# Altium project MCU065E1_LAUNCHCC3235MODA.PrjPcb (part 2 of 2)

## Sheet MCU065E1_XDS110_Circuit.SchDoc: XDS110_Circuit
size 431 x 279 mm; Date: Not shown in title block; ApprovedBy: Not shown in title block; CheckedBy: Not shown in title block; Author: Not shown in title block; CompanyName: Not shown in title block; DrawnBy: Seong Kim; Engineer: Not shown in title block; Organization: Not shown in title block; Address1: Not shown in title block; Address2: Not shown in title block; Address3: Not shown in title block; Address4: Not shown in title block; DocumentNumber: 2; Revision: Use project parameter SCH_Rev; SheetNumber: 2; SheetTotal: 6; PageSetup: Record=PageOptions¦CenterHorizontal=True¦CenterVertical=True¦PrintScale=1.00¦XCorrection=1.00¦YCorrection=1.00¦PrintKind=0¦BorderSize=5000000¦LeftOffset=0¦BottomOffset=0¦Orientation=2¦PaperLength=1000¦PaperWidth=1000¦Scale=100¦PaperSource=15¦PrintQuality=600¦MediaType=1¦DitherType=10¦PaperKind=Letter¦PrintScaleMode=1
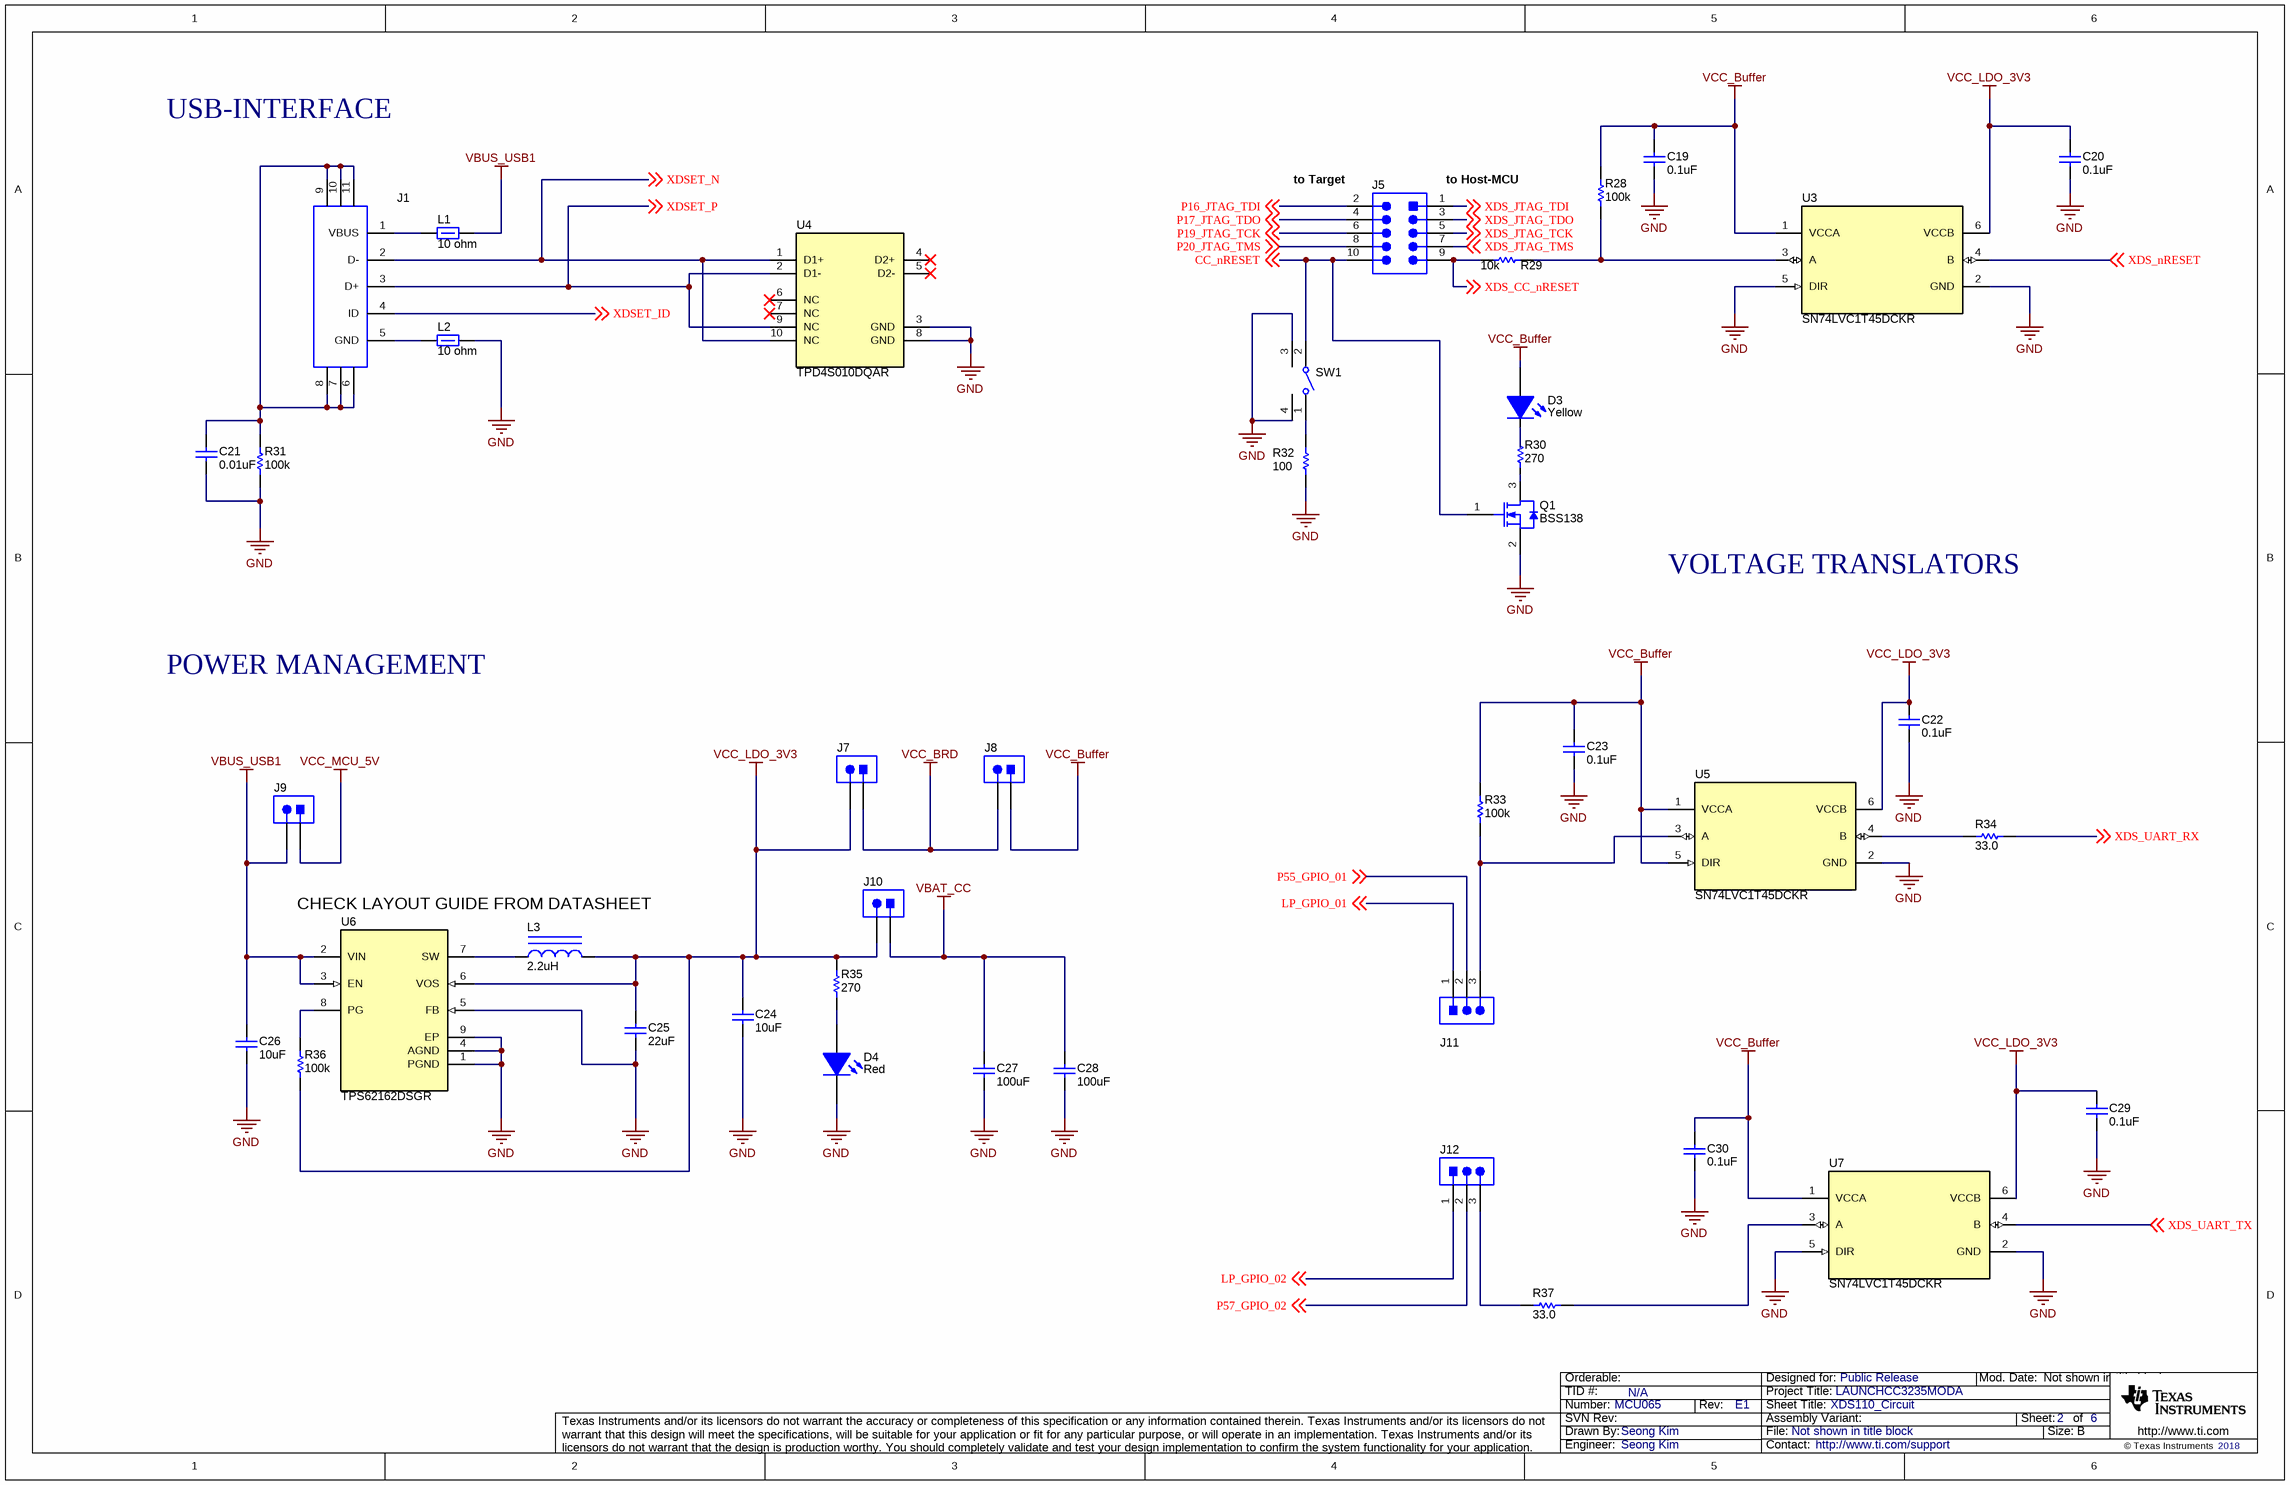
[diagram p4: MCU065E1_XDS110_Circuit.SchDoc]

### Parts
C19  ValueDisplayed: 0.1uF  [0402]  (hidden comment: GRM155R61A104KA01D)
C20  ValueDisplayed: 0.1uF  [0402]  (hidden comment: GRM155R61A104KA01D)
C21  ValueDisplayed: 0.01uF  [0402]  (hidden comment: GRM155R71C103KA01D)
C22  ValueDisplayed: 0.1uF  [0402]  (hidden comment: GRM155R61A104KA01D)
C23  ValueDisplayed: 0.1uF  [0402]  (hidden comment: GRM155R61A104KA01D)
C24  ValueDisplayed: 10uF  [0805]  (hidden comment: CMP-0008285-2)
C25  ValueDisplayed: 22uF  [0805_HV]  (hidden comment: CMP-0007826-2)
C26  ValueDisplayed: 10uF  [0805]  (hidden comment: CMP-0008285-2)
C27  ValueDisplayed: 100uF  [1206_180M]  (hidden comment: CMP-0008934-2)
C28  ValueDisplayed: 100uF  [1206_180]  (hidden comment: CMP-0008934-2)
C29  ValueDisplayed: 0.1uF  [0402]  (hidden comment: GRM155R61A104KA01D)
C30  ValueDisplayed: 0.1uF  [0402]  (hidden comment: GRM155R61A104KA01D)
D3  value Yellow  [WL-SMCW_YELLOW]  (hidden comment: CMP-0002892-2)
D4  value Red  [SML-31_Red]  (hidden comment: CMP-0002871-1)
J1  1051640001  [Molex_1051640001]  (value not drawn)
J5  61301021121  [WURTH_61301021121]  (value not drawn)
J7  CMP-0054794-1  [WURTH_61300211121]  (value not drawn)
J8  CMP-0054794-1  [WURTH_61300211121]  (value not drawn)
J9  CMP-0054794-1  [WURTH_61300211121]  (value not drawn)
J10  CMP-0054794-1  [WURTH_61300211121]  (value not drawn)
J11  61300311121  [WURTH_61300311121]  (value not drawn)
J12  61300311121  [WURTH_61300311121]  (value not drawn)
L1  ValueDisplayed: 10 ohm  [0402]  (hidden comment: BLM15AG100SN1D)
L2  ValueDisplayed: 10 ohm  [0402]  (hidden comment: BLM15AG100SN1D)
L3  ValueDisplayed: 2.2uH  [0805]  (hidden comment: CMP-0059580-1)
Q1  BSS138  [SOT-23]
R28  ValueDisplayed: 100k  [0402]  (hidden comment: CRCW0402100KJNED)
R29  ValueDisplayed: 10k  [0402]  (hidden comment: CRCW040210K0JNED)
R30  ValueDisplayed: 270  [0603]  (hidden comment: CMP-0025765-4)
R31  ValueDisplayed: 100k  [0603]  (hidden comment: CRCW0603100KJNEAC)
R32  ValueDisplayed: 100  [0402]  (hidden comment: CMP-0026656-1)
R33  ValueDisplayed: 100k  [0402]  (hidden comment: CRCW0402100KJNED)
R34  ValueDisplayed: 33.0  [0402]  (hidden comment: ERJ-2RKF33R0X)
R35  ValueDisplayed: 270  [0603]  (hidden comment: CMP-0025765-4)
R36  ValueDisplayed: 100k  [0402]  (hidden comment: CMP-0026823-3)
R37  ValueDisplayed: 33.0  [0402]  (hidden comment: ERJ-2RKF33R0X)
SW1  TL3330AF260QG  [SW_TL3330]  (value not drawn)
U3  SN74LVC1T45DCKR  [DCK0006A_N]
U4  TPD4S010DQAR  [DQA0010A]
U5  SN74LVC1T45DCKR  [DCK0006A_N]
U6  PartNumber: TPS62162DSGR  [DSG0008A]  (hidden comment: CMP-0037789-2)
U7  SN74LVC1T45DCKR  [DCK0006A_N]

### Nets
GND: C19.2 C20.2 C21.2 C22.2 C23.2 C24.2 C25.2 C26.2 C27.2 C28.2 C29.2 C30.2 D4.1(K) L2.2 Q1.2(S) R31.1 R32.1 SW1.3 SW1.4 U3.2(GND) U3.5(DIR) U4.3(GND) U4.8(GND) U5.2(GND) U6.1(PGND) U6.4(AGND) U6.5(FB) U6.9(EP) U7.2(GND) U7.5(DIR)
VBAT_CC: C27.1 C28.1 J10.1
VBUS_USB1: C26.1 J9.2 L1.2 U6.2(VIN) U6.3(EN)
VCC_BRD: J7.1 J8.2
VCC_Buffer: C19.1 C23.1 C30.1 D3.2(A) J8.1 R28.2 R33.2 U3.1(VCCA) U5.1(VCCA) U5.5(DIR) U7.1(VCCA)
VCC_LDO_3V3: C20.1 C22.1 C24.1 C25.1 C29.1 J7.2 J10.2 L3.2 R35.1 R36.2 U3.6(VCCB) U5.6(VCCB) U6.6(VOS) U7.6(VCCB)
VCC_MCU_5V: J9.1
CC_nRESET: J5.10 Q1.1(G) SW1.2 ; off-sheet CC_nRESET
LP_GPIO_01: J11.1 ; off-sheet LP_GPIO_01
LP_GPIO_02: J12.1 ; off-sheet LP_GPIO_02
P16_JTAG_TDI: J5.2 ; off-sheet P16_JTAG_TDI
P17_JTAG_TDO: J5.4 ; off-sheet P17_JTAG_TDO
P19_JTAG_TCK: J5.6 ; off-sheet P19_JTAG_TCK
P20_JTAG_TMS: J5.8 ; off-sheet P20_JTAG_TMS
P55_GPIO_01: J11.2 ; off-sheet P55_GPIO_01
P57_GPIO_02: J12.2 ; off-sheet P57_GPIO_02
XDS_CC_nRESET: J5.9 R29.1 ; off-sheet XDS_CC_nRESET
XDS_JTAG_TCK: J5.5 ; off-sheet XDS_JTAG_TCK
XDS_JTAG_TDI: J5.1 ; off-sheet XDS_JTAG_TDI
XDS_JTAG_TDO: J5.3 ; off-sheet XDS_JTAG_TDO
XDS_JTAG_TMS: J5.7 ; off-sheet XDS_JTAG_TMS
XDS_nRESET: U3.4(B) ; off-sheet XDS_nRESET
XDS_UART_RX: R34.2 ; off-sheet XDS_UART_RX
XDS_UART_TX: U7.4(B) ; off-sheet XDS_UART_TX
XDSET_ID: J1.4(ID) ; off-sheet XDSET_ID
XDSET_N: J1.2(D-) U4.1(D1+) U4.10(NC) ; off-sheet XDSET_N
XDSET_P: J1.3(D+) U4.2(D1-) U4.9(NC) ; off-sheet XDSET_P
NetC21_1: C21.1 J1.6 J1.7 J1.8 J1.9 J1.10 J1.11 R31.2
NetD3_1: D3.1(K) R30.2
NetD4_2: D4.2(A) R35.2
NetJ1_1: J1.1(VBUS) L1.1
NetJ1_5: J1.5(GND) L2.1
NetJ11_3: J11.3 R33.1 U5.3(A)
NetJ12_3: J12.3 R37.1
NetL3_1: L3.1 U6.7(SW)
NetQ1_3: Q1.3(D) R30.1
NetR28_1: R28.1 R29.2 U3.3(A)
NetR32_2: R32.2 SW1.1
NetR34_1: R34.1 U5.4(B)
NetR36_1: R36.1 U6.8(PG)
NetR37_2: R37.2 U7.3(A)

Not connected (* = marked no-connect by the designer): U4 4(D2+)* 5(D2-)* 6(NC)* 7(NC)*

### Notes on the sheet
- USB-INTERFACE
- (near J5) to Target
- (near J5) to Host-MCU
- VOLTAGE TRANSLATORS
- POWER MANAGEMENT
- CHECK LAYOUT GUIDE FROM DATASHEET

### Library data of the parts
C19 C20 C22 C23 C29 C30 = CMP-0006562-2: CAP, CERM, 0.1 uF, 10 V, +/- 10%, X5R, 0402; Manufacturer: MuRata; TaMin_C: -55°C; Polarized: N; SizeAreaWB_mm2: 3; Value1: Unknown; U/M: EA; Value: 0.1uF; TaMax_C: 85°C; SizeZ_mm: 0.6; SizeX_mm: 1; SizeY_mm: 0.5; Value2: 10V; CompType: Capacitor; Cap_F: 100nF; AEC Category: Q200
C21 = CMP-0006639-2: CAP, CERM, 0.01 uF, 16 V, +/- 10%, X7R, 0402; Manufacturer: MuRata; TaMin_C: -55°C; Polarized: N; SizeAreaWB_mm2: 3; Value1: Unknown; U/M: EA; Value: 0.01uF; TaMax_C: 125°C; SizeZ_mm: 0.6; SizeX_mm: 1; SizeY_mm: 0.5; Value2: 16V; CompType: Capacitor; Cap_F: 10nF; AEC Category: Q200
C24 C26 = CMP-0008285-2: CAP, CERM, 10 uF, 10 V, +/- 10%, X5R, 0805; PartNumber: GRM21BR61A106KE19L; Manufacturer: MuRata; Alternate PartNumber: CL21A106KPFNNNE; Alternate Manufacturer: SAMSUNG; Polarized: N; CompType: Capacitor; Value: 10uF; U/M: EA; Cap_F: 10µF; ESR_ohm: 2m; Value1: 0.002 ohm; VDC_V: 10V; TaMin_C: -55°C; TaMax_C: 85°C; SizeAreaWB_mm2: 6.75; SizeZ_mm: 1.45; SizeX_mm: 2; SizeY_mm: 1.25; SizeArea_mm2: 2.5; AEC Category: Q200
C25 = CMP-0007826-2: CAP, CERM, 22 uF, 16 V, +/- 10%, X5R, 0805; PartNumber: C2012X5R1C226K125AC; Manufacturer: TDK; Alternate PartNumber: ----; Polarized: N; CompType: Capacitor; Value: 22uF; U/M: EA; Cap_F: 22µF; Value1: Unknown; VDC_V: 16V; TaMin_C: -55°C; TaMax_C: 85°C; Cap_Case: 0805; AEC Category: Q200; SizeAreaWB_mm2: 6.75; SizeZ_mm: 1.45; SizeX_mm: 2; SizeY_mm: 1.25; SizeArea_mm2: 2.5
C27 C28 = CMP-0008934-2: CAP, CERM, 100 uF, 6.3 V, +/- 20%, X5R, 1206; PartNumber: GRM31CR60J107ME39L; Manufacturer: MuRata; Alternate PartNumber: CL31A107MQHNNNE; Alternate Manufacturer: SAMSUNG; Polarized: N; CompType: Capacitor; Value: 100uF; U/M: EA; Cap_F: 100µF; ESR_ohm: 3m; Value1: 0.003 ohm; VDC_V: 6.3V; TaMin_C: -55°C; TaMax_C: 85°C; Cap_Case: 1206; SizeAreaWB_mm2: 10.92; SizeZ_mm: 1.8; SizeX_mm: 3.2; SizeY_mm: 1.6; SizeArea_mm2: 5.12; AEC Category: Q200
D3 = CMP-0002892-2: LED, Yellow, SMD; Manufacturer: Wurth Elektronik; PartNumber: 150060YS75000; Alternate Manufacturer: Everlight; Alternate PartNumber: 19-217/G7C-AN1P2/3T; Type: AlInGaP; Vf_V: 2V; Io_A: 20mA; Value1: W; U/M: EA
D4 = CMP-0002871-1: LED, Red, SMD; Manufacturer: Rohm; PartNumber: SML-311UTT86; Alternate Manufacturer: Everlight; Alternate PartNumber: 19-217/R6C-AL1M2VY/3T; Type: AlInGaP; Vf_V: 1.8V; Io_A: 2mA; Value1: W; U/M: EA
J1 = CMP-0055311-1: Receptacle, USB 2.0, Micro B, 5 Position, R/A, SMT; Manufacturer: Molex; CNHeader: FALSE; Current_A: 1.8A; Gender: Female; Voltage_V: 30V; Pitch_mm: 0.65; ContactFinish: Gold; CT: TRUE; Cert_UL: Y
J5 = CMP-0054806-3: Header, 2.54 mm, 5x2, Gold, TH; Manufacturer: Wurth Elektronik; Green_Lifecycle: Active; Green_REACh: Passed; Cert_UL: Y; Current_A: 3A; Gender: Male; Pitch_mm: 2.54; Row_Count: 2; Shrouded: N; Voltage_V: 250V
J7-J10 = CMP-0054794-1: Header, 2.54 mm, 2x1, Gold, TH; PartNumber: 61300211121; Manufacturer: Wurth Elektronik; CNHeader: TRUE; Green_Lifecycle: Active; Green_REACh: Passed; CT: FALSE
J11 J12 = CMP-0054796-1: Header, 2.54 mm, 3x1, Gold, TH; Manufacturer: Wurth Elektronik; CNHeader: TRUE; Green_Lifecycle: Active; Green_REACh: Passed; CT: FALSE
L1 L2 = CMP-0003309-1: Ferrite Bead, 10 ohm @ 100 MHz, 1 A, 0402; Manufacturer: MuRata; ZTyp@100MHz_Ohm: 10; SizeAreaWB_mm2: 3; DCR_ohm: 0.025; Value1: 0.025 ohm; Value: 10 ohm; Imax_A: 1A; SizeZ_mm: 0.6; SizeX_mm: 1; SizeY_mm: 0.5
L3 = CMP-0059580-1: Inductor, Wirewound, 2.2 uH, 1 A, 0.143 ohm, SMD; PartNumber: BRC2012T2R2MD; Manufacturer: Taiyo Yuden; Alternate PartNumber: ----; Value: 2.2uH; Ind_H: 2.2µH; Imax_A: 1A; Irms: 1A @ 40C rise; Isat: 1.1A @ 30% inductance drop; DCR_ohm: 1.43d; AEC Category: Q200; Green_Lifecycle: Active; SizeAreaWB_mm2: 6.75; Green_REACh: Passed; SizeZ_mm: 1.45; SizeX_mm: 2; SizeY_mm: 1.25; SizeArea_mm2: 2.5
Q1 = CMP-0000755-1: MOSFET, N-CH, 50 V, 0.22 A, SOT-23; Alternate Manufacturer: None; Manufacturer: Fairchild Semiconductor; SizeZ_mm: 1.1; ChType: N; Value2: 1.7 nC; VdsMax_V: 50V; SizeX_mm: 2.5; SizeY_mm: 3; Vgs_V: 20V; Value: 50V; Rdson45_ohm: 6; SizeArea_mm2: 7.5; AEC Category: Q101; IdsMax_A: 2.2dA; SizeAreaWB_mm2: 14; U/M: EA; QgTyp_nC: 1.7
R28 R33 = CMP-0026823-3: RES, 100 k, 5%, 0.063 W, AEC-Q200 Grade 0, 0402; Manufacturer: Vishay-Dale; Power_W: 63mW; TempCo: 200 ppm/C; Value: 100k; EIA_Code: E24; SizeX_mm: 1; SizeY_mm: 0.5; SizeZ_mm: 0.6; Value2: 0.063W; CompType: Resistor; AEC Qualified: Y; VDC_V: 50V; AEC Category: Q200; AEC Grade: 0
R29 = CMP-0026825-5: RES, 10 k, 5%, 0.063 W, AEC-Q200 Grade 0, 0402; Manufacturer: Vishay-Dale; Power_W: 63mW; TempCo: 200 ppm/C; Value_Code: 10k0; Value: 10k; EIA_Code: E24; SizeX_mm: 1; SizeY_mm: 0.5; SizeZ_mm: 0.6; Value2: 0.063W; CompType: Resistor; AEC Qualified: Y; VDC_V: 50V; AEC Category: Q200; AEC Grade: 0
R30 R35 = CMP-0025765-4: RES, 270, 5%, 0.1 W, AEC-Q200 Grade 0, 0603; PartNumber: CRCW0603270RJNEA; Manufacturer: Vishay-Dale; CompType: Resistor; Value: 270; Value_Code: 270R; Power_W: 100mW; Value2: 0.1W; VDC_V: 75V; TempCo: 200 ppm/C; EIA_Code: E24; SizeX_mm: 1.6; SizeY_mm: 0.8; SizeZ_mm: 1; SizeArea_mm2: 1.28; AEC Qualified: Y; AEC Category: Q200; AEC Grade: 0
R31 = CMP-0082530-1: RES, 100 k, 5%, 0.1 W, 0603; Manufacturer: Vishay-Dale; Power_W: 100mW; TempCo: 200 ppm/C; SizeAreaWB_mm2: 4.68; Value: 100k; EIA_Code: E24; SizeX_mm: 1.6; SizeY_mm: 0.8; SizeZ_mm: 1; Value2: 0.1W; SizeArea_mm2: 1.28; CompType: Resistor; AEC Qualified: N; VDC_V: 75V; AEC Category: Q200
R32 = CMP-0026656-1: RES, 100, 1%, 0.1 W, 0402; PartNumber: ERJ-2RKF1000X; Manufacturer: Panasonic; Alternate Manufacturer: YAGEO; Alternate PartNumber: RC0402FR-07100RL; CompType: Resistor; Value: 100; Value_Code: 100R; Power_W: 100mW; Value2: 0.1W; VDC_V: 50V; TempCo: 100 ppm/C; EIA_Code: E96; U/M: EA; SizeX_mm: 1; SizeY_mm: 0.5; SizeZ_mm: 0.6; AEC Category: Q200
R34 R37 = CMP-0026696-1: RES, 33.0, 1%, 0.1 W, 0402; Manufacturer: Panasonic; Power_W: 100mW; TempCo: 100 ppm/C; Value_Code: 33R0; U/M: EA; Value: 33.0; Res_ohm: 33; SizeX_mm: 1; SizeY_mm: 0.5; SizeZ_mm: 0.6; Value2: 0.1W; CompType: Resistor; VDC_V: 50V; AEC Category: Q200
R36 = CMP-0026823-3: RES, 100 k, 5%, 0.063 W, AEC-Q200 Grade 0, 0402; PartNumber: CRCW0402100KJNED; Manufacturer: Vishay-Dale; CompType: Resistor; Value: 100k; Power_W: 63mW; Value2: 0.063W; VDC_V: 50V; TempCo: 200 ppm/C; EIA_Code: E24; SizeX_mm: 1; SizeY_mm: 0.5; SizeZ_mm: 0.6; AEC Qualified: Y; AEC Category: Q200; AEC Grade: 0
SW1 = CMP-0002231-1: Switch, SPST-NO,  1 Pos, 0.05A, 12VDC, SMD; Manufacturer: E-Switch; CurrentRating_mA: 50A; PositionCount: 1; VDC_V: 12V; SwitchFunction: Off-Mom
U3 U5 U7 = CMP-0051039-3: Single-Bit Dual-Supply Bus Transceiver with Configurable Voltage Translation and 3-State Outputs, DCK0006A, LARGE T&R; Manufacturer: Texas Instruments; Alternate PartNumber: SN74LVC1T45DCKT; Output Type: CMOS; Bits(#): 1; Input Type: CMOS/TTL; Technology Family: LVC; Schmitt Trigger: No; 3-State Output: Yes; VCC(Max)(V): 5.5; Sub-Family: Dual Supply Translator; Rating: Catalog; Output Drive (IOL/IOH)(Max)(mA): 32/-32; ICC @ Nom Voltage(Max)(mA): 0.004; VCC(Min)(V): 1.65; F @ Nom Voltage(Max)(Mhz): 150; Logic: True; Voltage(Nom)(V): 1.8,2.5,3.3,5; tpd @ Nom Voltage(Max)(ns): 15.5,8,5.8,4.4; AEC Category: Q200; AEC Qualified: N; CompType: IC; SizeAreaWB_mm2: 9.3; SizeArea_mm2: 4.2; SizeX_mm: 2.1; SizeY_mm: 2; SizeZ_mm: 1.1
U4 = CMP-0043121-2: ESD Solution for High-Speed Differential Interface, 4 Channels, -40 to +85 degC,10-pin SON (DQA), Green (RoHS & no Sb/Br); Manufacturer: Texas Instruments; IO Leakage Current(nA): 10; IO Capacitance(Typ)(pF): 0.8; 1394 / Firewire: TRUE; Breakdown Voltage(Min)(V): 9; Differential Capacitance(pF): 0.05; IEC 61000-4-2 Contact(+/- kV): 8
U6 = CMP-0037789-2: Buck Step Down Regulator with 3 to 17 V Input and 3.3 V Output, -40 to 85 degC, 8-Pin WSON (DSG), Green (RoHS & no Sb/Br); Manufacturer: Texas Instruments; Duty Cycle(Max)(%): 100; Iout(Max)(A): 1; Iq(Typ)(mA): 0.017; Preset Vout(V): 3.3; Rating: Catalog; SubFamily: Step-Down Regulator; Switch Current Limit(Typ)(A): 1.8; Synchronous Rectification: TRUE; Vin(Max)(V): 17; Vin(Min)(V): 3

## Sheet MCU065E1_XDS110_Host.SchDoc: XDS110_Host
size 431 x 279 mm; Date: Not shown in title block; ApprovedBy: Not shown in title block; CheckedBy: Not shown in title block; Author: Not shown in title block; CompanyName: Not shown in title block; DrawnBy: Seong Kim; Engineer: Not shown in title block; Organization: Not shown in title block; Address1: Not shown in title block; Address2: Not shown in title block; Address3: Not shown in title block; Address4: Not shown in title block; DocumentNumber: 1; Revision: Use project parameter SCH_Rev; SheetNumber: 1; SheetTotal: 6; PageSetup: Record=PageOptions¦CenterHorizontal=True¦CenterVertical=True¦PrintScale=1.00¦XCorrection=1.00¦YCorrection=1.00¦PrintKind=0¦BorderSize=5000000¦LeftOffset=0¦BottomOffset=0¦Orientation=2¦PaperLength=1000¦PaperWidth=1000¦Scale=100¦PaperSource=15¦PrintQuality=600¦MediaType=1¦DitherType=10¦PaperKind=Letter¦PrintScaleMode=1
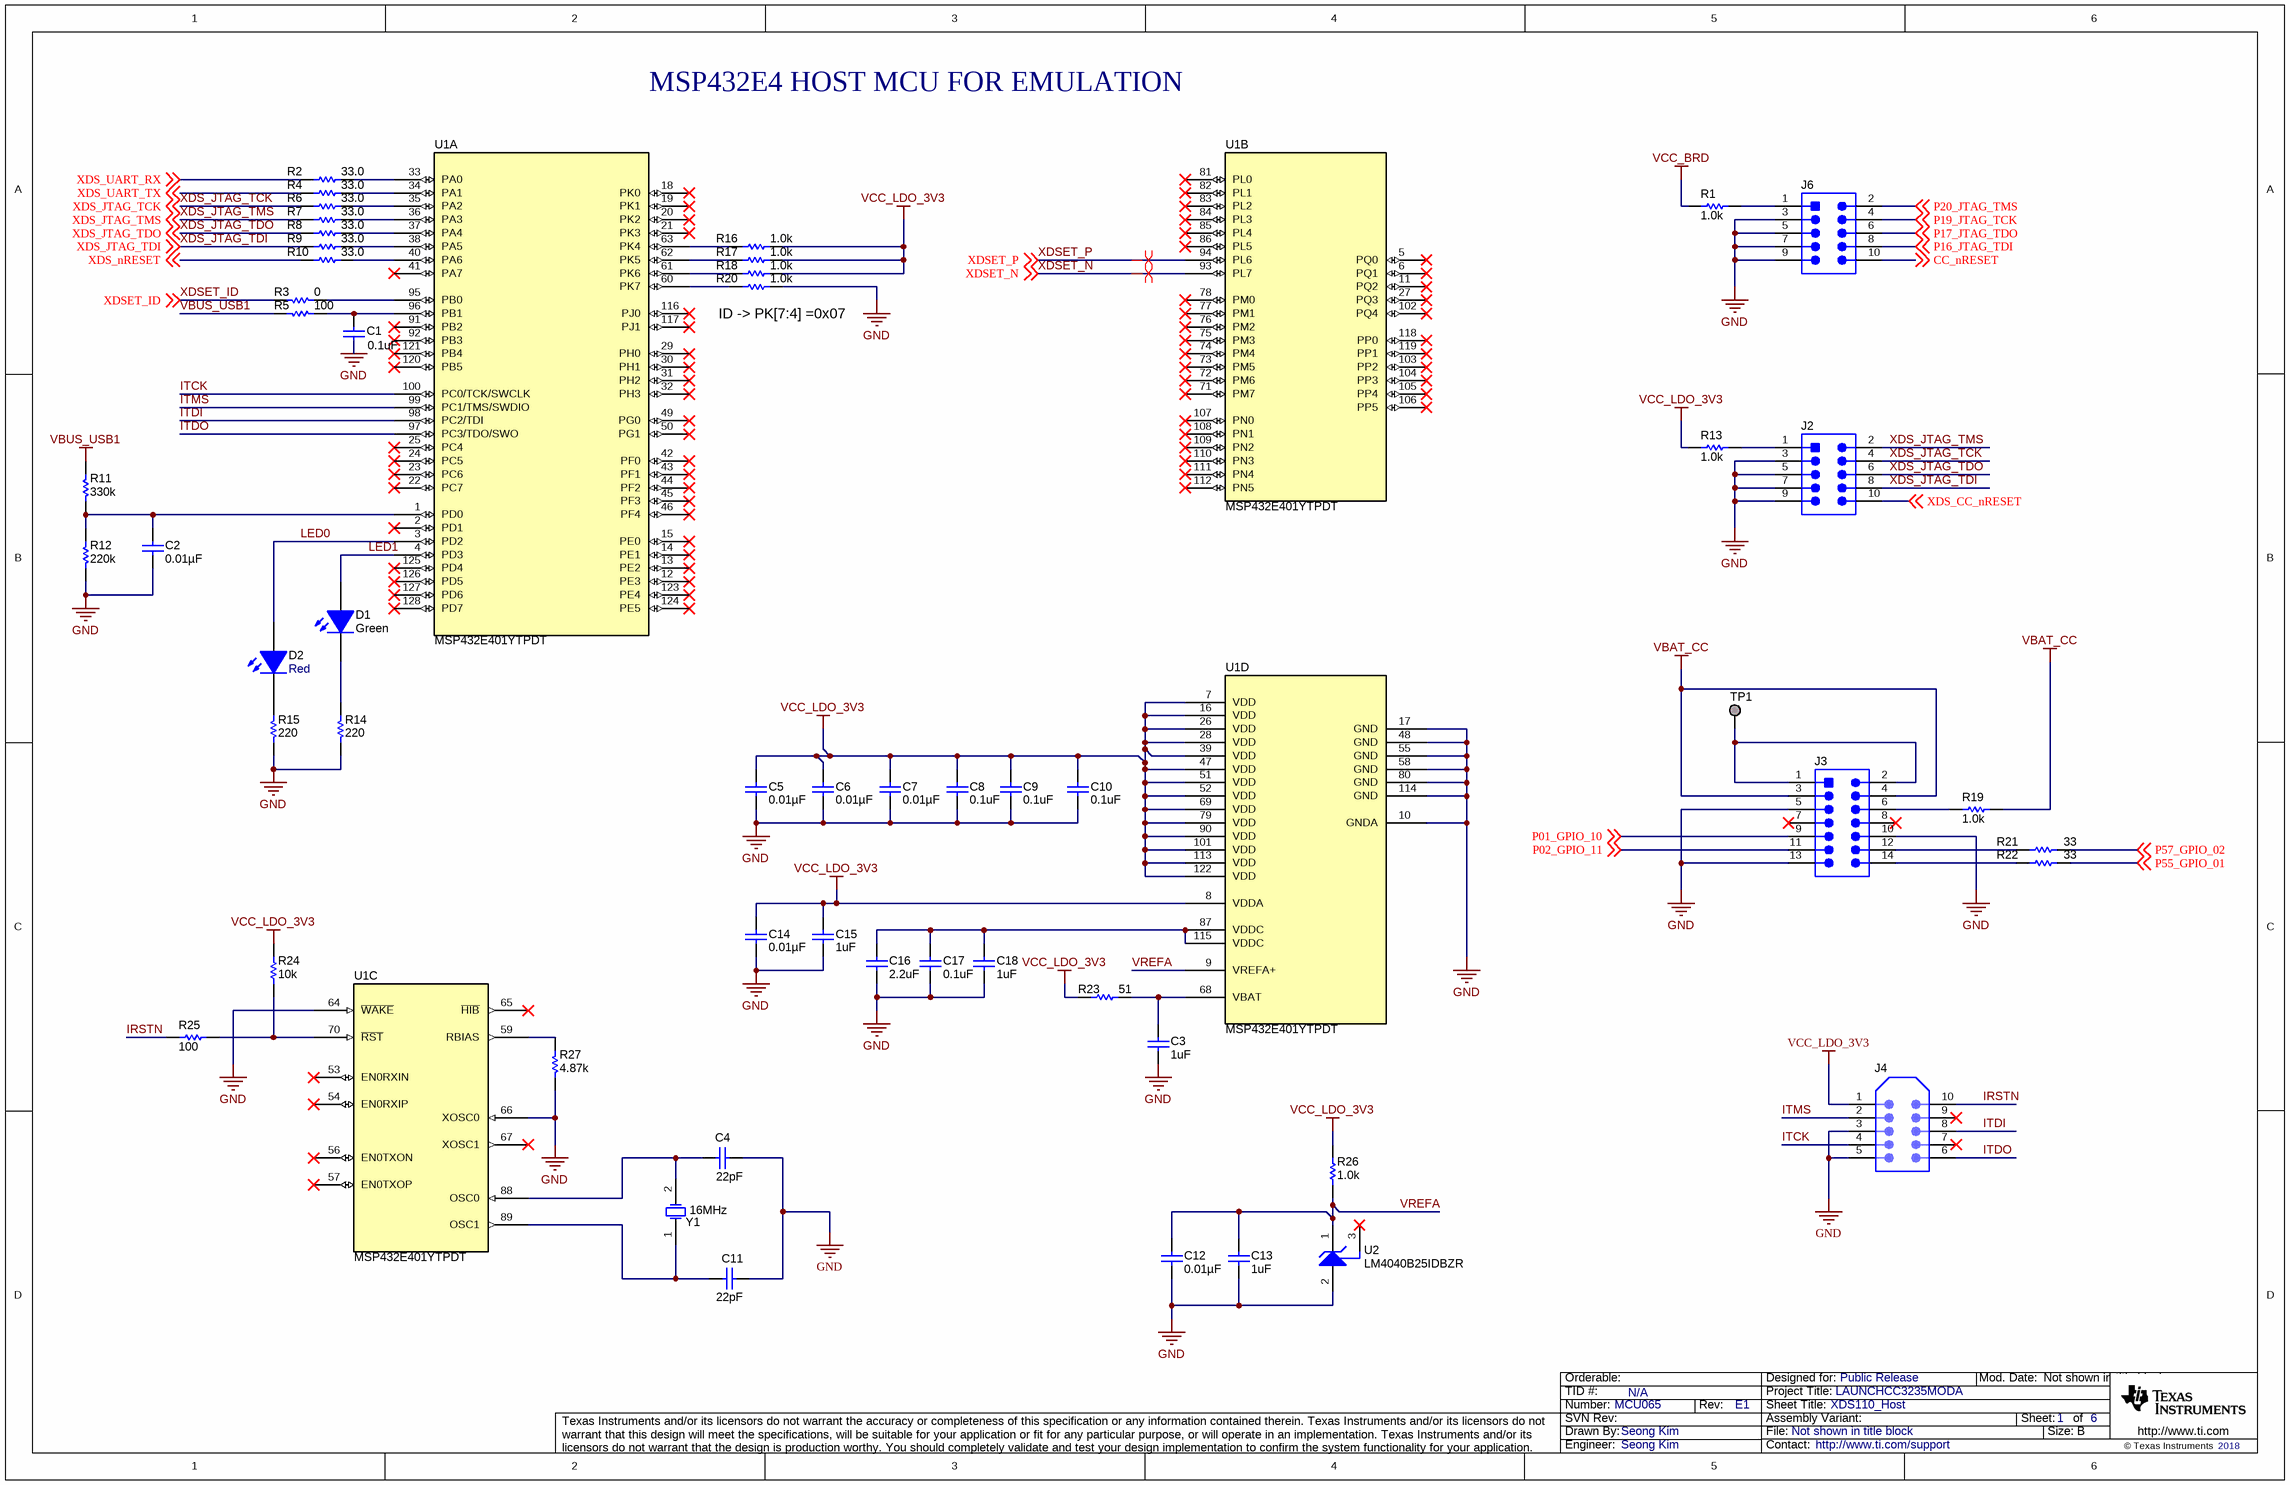
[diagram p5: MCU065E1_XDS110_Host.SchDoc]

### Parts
C1  ValueDisplayed: 0.1uF  [0402]  (hidden comment: LMK105BJ104KV-F)
C2  ValueDisplayed: 0.01µF  [0402]  (hidden comment: CL05B103KO5NNNC)
C3  ValueDisplayed: 1uF  [0402]  (hidden comment: EMK105BJ105KVHF)
C4  ValueDisplayed: 22pF  [0402]  (hidden comment: CL05C220JB5NNNC)
C5  ValueDisplayed: 0.01µF  [0402]  (hidden comment: CL05B103KO5NNNC)
C6  ValueDisplayed: 0.01µF  [0402]  (hidden comment: CL05B103KO5NNNC)
C7  ValueDisplayed: 0.01µF  [0402]  (hidden comment: CL05B103KO5NNNC)
C8  ValueDisplayed: 0.1uF  [0603]  (hidden comment: 06033D104KAT2A)
C9  ValueDisplayed: 0.1uF  [0603]  (hidden comment: 06033D104KAT2A)
C10  ValueDisplayed: 0.1uF  [0603]  (hidden comment: 06033D104KAT2A)
C11  ValueDisplayed: 22pF  [0402]  (hidden comment: CL05C220JB5NNNC)
C12  ValueDisplayed: 0.01µF  [0402]  (hidden comment: CL05B103KO5NNNC)
C13  ValueDisplayed: 1uF  [0402]  (hidden comment: EMK105BJ105KVHF)
C14  ValueDisplayed: 0.01µF  [0402]  (hidden comment: CL05B103KO5NNNC)
C15  ValueDisplayed: 1uF  [0402]  (hidden comment: EMK105BJ105KVHF)
C16  ValueDisplayed: 2.2uF  [0402]  (hidden comment: C1005X5R1C225K050BC)
C17  ValueDisplayed: 0.1uF  [0603]  (hidden comment: 06033D104KAT2A)
C18  ValueDisplayed: 1uF  [0402]  (hidden comment: EMK105BJ105KVHF)
D1  value Green  [LED_SML-LX0603GW]  (hidden comment: SML-LX0603GW-TR)
D2  value Red  [19-217_R6C-AL1M2VY_3T_Red]  (hidden comment: 19-217/R6C-AL1M2VY/3T)
J2  CMP-0075533-1  [Samtec_FTSH-105-01-x-D-K]  (value not drawn)
J3  CMP-0055564-1  [Samtec_FTSH-107-01-x-DV]  (value not drawn)
J4  CMP-0075101-1  [Tag_TC2050-NL]  (value not drawn)  (no BOM)
J6  CMP-0075533-1  [Samtec_FTSH-105-01-x-D-K]  (value not drawn)
R1  ValueDisplayed: 1.0k  [0402]  (hidden comment: CMP-0026852-3)
R2  ValueDisplayed: 33.0  [0402]  (hidden comment: ERJ-2RKF33R0X)
R3  ValueDisplayed: 0  [0402]  (hidden comment: ERJ-2GE0R00X)
R4  ValueDisplayed: 33.0  [0402]  (hidden comment: ERJ-2RKF33R0X)
R5  ValueDisplayed: 100  [0402]  (hidden comment: CRCW0402100RJNED)
R6  ValueDisplayed: 33.0  [0402]  (hidden comment: ERJ-2RKF33R0X)
R7  ValueDisplayed: 33.0  [0402]  (hidden comment: ERJ-2RKF33R0X)
R8  ValueDisplayed: 33.0  [0402]  (hidden comment: ERJ-2RKF33R0X)
R9  ValueDisplayed: 33.0  [0402]  (hidden comment: ERJ-2RKF33R0X)
R10  ValueDisplayed: 33.0  [0402]  (hidden comment: ERJ-2RKF33R0X)
R11  ValueDisplayed: 330k  [0402]  (hidden comment: CRCW0402330KJNED)
R12  ValueDisplayed: 220k  [0402]  (hidden comment: CRCW0402220KJNED)
R13  ValueDisplayed: 1.0k  [0402]  (hidden comment: CMP-0026852-3)
R14  ValueDisplayed: 220  [0603]  (hidden comment: CRCW0603220RJNEA)
R15  ValueDisplayed: 220  [0603]  (hidden comment: CRCW0603220RJNEA)
R16  ValueDisplayed: 1.0k  [0402]  (hidden comment: CRCW04021K00JNED)
R17  ValueDisplayed: 1.0k  [0402]  (hidden comment: CRCW04021K00JNED)
R18  ValueDisplayed: 1.0k  [0402]  (hidden comment: CRCW04021K00JNED)
R19  ValueDisplayed: 1.0k  [0402]  (hidden comment: CMP-0026852-3)
R20  ValueDisplayed: 1.0k  [0402]  (hidden comment: CRCW04021K00JNED)
R21  ValueDisplayed: 33  [0603]  (hidden comment: CMP-0025787-4)
R22  ValueDisplayed: 33  [0603]  (hidden comment: CMP-0025787-4)
R23  ValueDisplayed: 51  [0402]  (hidden comment: CRCW040251R0JNED)
R24  ValueDisplayed: 10k  [0402]  (hidden comment: CRCW040210K0JNED)
R25  ValueDisplayed: 100  [0402]  (hidden comment: CRCW0402100RFKED)
R26  ValueDisplayed: 1.0k  [0402]  (hidden comment: CRCW04021K00JNED)
R27  ValueDisplayed: 4.87k  [0603]  (hidden comment: CRCW06034K87FKEA)
TP1  CMP-0078143-2  [TESTPOINT]  (value not drawn)  (no BOM)
U1  MSP432E401YTPDT  [PDT0128A]  (parts A,B,C,D of 4)
U2  LM4040B25IDBZR  [DBZ0003A_N]
Y1  Frequency_Fixed: 16MHz  [XTAL_ABM3]  (hidden comment: CMP-0004648-3)

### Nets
GND: C1.2 C2.2 C3.1 C4.1 C5.2 C6.2 C7.2 C8.2 C9.2 C10.2 C11.1 C12.2 C13.2 C14.2 C15.2 C16.2 C17.2 C18.2 J2.3 J2.5 J2.7 J2.9 J3.5 J3.10 J3.13 J4.3 J4.5 J6.3 J6.5 J6.7 J6.9 R12.1 R14.1 R15.1 R20.2 R27.1 U1.10(GNDA) U1.17(GND) U1.48(GND) U1.55(GND) U1.58(GND) U1.64(~{WAKE}) U1.66(XOSC0) U1.80(GND) U1.114(GND) U2.2(ANODE)
VBAT_CC: J3.3 J3.4 R19.2
VBUS_USB1: R5.2 R11.2
VCC_BRD: R1.1
VCC_LDO_3V3: C5.1 C6.1 C7.1 C8.1 C9.1 C10.1 C14.1 C15.1 J4.1 R13.1 R16.2 R17.2 R18.2 R23.1 R24.2 R26.2 U1.7(VDD) U1.8(VDDA) U1.16(VDD) U1.26(VDD) U1.28(VDD) U1.39(VDD) U1.47(VDD) U1.51(VDD) U1.52(VDD) U1.69(VDD) U1.79(VDD) U1.90(VDD) U1.101(VDD) U1.113(VDD) U1.122(VDD)
CC_nRESET: J6.10 ; off-sheet CC_nRESET
IRSTN: J4.10 R25.1
ITCK: J4.4 U1.100(PC0/TCK/SWCLK)
ITDI: J4.8 U1.98(PC2/TDI)
ITDO: J4.6 U1.97(PC3/TDO/SWO)
ITMS: J4.2 U1.99(PC1/TMS/SWDIO)
LED0: D2.1(A) U1.3(PD2)
LED1: D1.1(A) U1.4(PD3)
P01_GPIO_10: J3.9 ; off-sheet P01_GPIO_10
P02_GPIO_11: J3.11 ; off-sheet P02_GPIO_11
P16_JTAG_TDI: J6.8 ; off-sheet P16_JTAG_TDI
P17_JTAG_TDO: J6.6 ; off-sheet P17_JTAG_TDO
P19_JTAG_TCK: J6.4 ; off-sheet P19_JTAG_TCK
P20_JTAG_TMS: J6.2 ; off-sheet P20_JTAG_TMS
P55_GPIO_01: R22.1 ; off-sheet P55_GPIO_01
P57_GPIO_02: R21.1 ; off-sheet P57_GPIO_02
VREFA: C12.1 C13.1 R26.1 U1.9(VREFA+) U2.1(CATHODE)
XDS_CC_nRESET: J2.10 ; off-sheet XDS_CC_nRESET
XDS_JTAG_TCK: J2.4 R6.1 ; off-sheet XDS_JTAG_TCK
XDS_JTAG_TDI: J2.8 R9.1 ; off-sheet XDS_JTAG_TDI
XDS_JTAG_TDO: J2.6 R8.1 ; off-sheet XDS_JTAG_TDO
XDS_JTAG_TMS: J2.2 R7.1 ; off-sheet XDS_JTAG_TMS
XDS_nRESET: R10.1 ; off-sheet XDS_nRESET
XDS_UART_RX: R2.1 ; off-sheet XDS_UART_RX
XDS_UART_TX: R4.1 ; off-sheet XDS_UART_TX
XDSET_ID: R3.2 ; off-sheet XDSET_ID
XDSET_N: U1.93(PL7) ; off-sheet XDSET_N
XDSET_P: U1.94(PL6) ; off-sheet XDSET_P
NetC1_1: C1.1 R5.1 U1.96(PB1)
NetC2_1: C2.1 R11.1 R12.2 U1.1(PD0)
NetC3_2: C3.2 R23.2 U1.68(VBAT)
NetC4_2: C4.2 U1.88(OSC0) Y1.2(OSC2)
NetC11_2: C11.2 U1.89(OSC1) Y1.1(OSC1)
NetC16_1: C16.1 C17.1 C18.1 U1.87(VDDC) U1.115(VDDC)
NetD1_2: D1.2(K) R14.2
NetD2_2: D2.2(K) R15.2
NetJ2_1: J2.1 R13.2
NetJ3_1: J3.1 J3.2 TP1.1
NetJ3_6: J3.6 R19.1
NetJ3_12: J3.12 R21.2
NetJ3_14: J3.14 R22.2
NetJ6_1: J6.1 R1.2
NetR2_2: R2.2 U1.33(PA0)
NetR3_1: R3.1 U1.95(PB0)
NetR4_2: R4.2 U1.34(PA1)
NetR6_2: R6.2 U1.35(PA2)
NetR7_2: R7.2 U1.36(PA3)
NetR8_2: R8.2 U1.37(PA4)
NetR9_2: R9.2 U1.38(PA5)
NetR10_2: R10.2 U1.40(PA6)
NetR16_1: R16.1 U1.63(PK4)
NetR17_1: R17.1 U1.62(PK5)
NetR18_1: R18.1 U1.61(PK6)
NetR20_1: R20.1 U1.60(PK7)
NetR24_1: R24.1 R25.2 U1.70(~{RST})
NetR27_2: R27.2 U1.59(RBIAS)

Not connected (* = marked no-connect by the designer): J3 7* 8*; J4 7* 9*; U1 2(PD1)* 5(PQ0)* 6(PQ1)* 11(PQ2)* 12(PE3)* 13(PE2)* 14(PE1)* 15(PE0)* 18(PK0)* 19(PK1)* 20(PK2)* 21(PK3)* 22(PC7)* 23(PC6)* 24(PC5)* 25(PC4)* 27(PQ3)* 29(PH0)* 30(PH1)* 31(PH2)* 32(PH3)* 41(PA7)* 42(PF0)* 43(PF1)* 44(PF2)* 45(PF3)* 46(PF4)* 49(PG0)* 50(PG1)* 53(EN0RXIN)* 54(EN0RXIP)* 56(EN0TXON)* 57(EN0TXOP)* 65(~{HIB})* 67(XOSC1)* 71(PM7)* 72(PM6)* 73(PM5)* 74(PM4)* 75(PM3)* 76(PM2)* 77(PM1)* 78(PM0)* 81(PL0)* 82(PL1)* 83(PL2)* 84(PL3)* 85(PL4)* 86(PL5)* 91(PB2)* 92(PB3)* 102(PQ4)* 103(PP2)* 104(PP3)* 105(PP4)* 106(PP5)* 107(PN0)* 108(PN1)* 109(PN2)* 110(PN3)* 111(PN4)* 112(PN5)* 116(PJ0)* 117(PJ1)* 118(PP0)* 119(PP1)* 120(PB5)* 121(PB4)* 123(PE4)* 124(PE5)* 125(PD4)* 126(PD5)* 127(PD6)* 128(PD7)*; U2 3(NC)*

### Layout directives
differential pair: XDSET_N, XDSET_P

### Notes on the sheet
- MSP432E4 HOST MCU FOR EMULATION
- ID -> PK[7:4] =0x07

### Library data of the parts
C1 = CMP-0064930-2: CAP, CERM, 0.1 uF, 10 V,+/- 10%, X5R, 0402; Manufacturer: Taiyo Yuden; TaMin_C: -55°C; Polarized: N; SizeAreaWB_mm2: 3; Value1: Unknown; U/M: EA; Value: 0.1uF; TaMax_C: 85°C; SizeZ_mm: 0.6; SizeX_mm: 1; SizeY_mm: 0.5; Value2: 10V; Cap_F: 100nF; AEC Category: Q200
C2 C5-C7 C12 C14 = CMP-0860186-1: CAP, CERM, 0.01 µF, 16 V,+/- 10%, X7R, 0402; Manufacturer: Samsung Electro-Mechanics; SizeAreaWB_mm2: 3; SizeArea_mm2: 0.5; Polarized: N; Value2: 16V; SizeX_mm: 1; AEC Category: Q200; U/M: EA; Value: 0.01uF; TaMin_C: -55°C; Cap_F: 10nF; TaMax_C: 125°C; SizeZ_mm: 0.6
C3 C13 C15 C18 = CMP-0006347-2: CAP, CERM, 1 uF, 16 V, +/- 10%, X5R, 0402; Manufacturer: Taiyo Yuden; TaMin_C: -55°C; Polarized: N; SizeAreaWB_mm2: 3; Value1: Unknown; U/M: EA; Value: 1uF; TaMax_C: 85°C; SizeZ_mm: 0.6; SizeX_mm: 1; SizeY_mm: 0.5; Value2: 16V; CompType: Capacitor; Cap_F: 1µF; AEC Category: Q200
C4 C11 = CMP-0085851-1: CAP, CERM, 22 pF, 50 V,+/- 5%, C0G/NP0, 0402; Manufacturer: Walsin; AEC Qualified: N; TaMax_C: 125°C; SizeX_mm: 1; Value: 22pF; SizeZ_mm: 0.6; Value2: 50V; AEC Category: Q200; TaMin_C: -55°C; SizeArea_mm2: 0.5; SizeAreaWB_mm2: 3; U/M: EA
C8-C10 C17 = CMP-0006758-5: CAP, CERM, 0.1 uF, 25 V, +/- 10%, X5R, 0603; Manufacturer: AVX; TaMin_C: -55°C; ESR_ohm: 0.048; Polarized: N; SizeAreaWB_mm2: 4.68; Value1: 0.048 ohm; U/M: EA; Value: 0.1uF; TaMax_C: 85°C; SizeZ_mm: 1; SizeX_mm: 1.6; SizeY_mm: 0.8; Value2: 25V; SizeArea_mm2: 1.28; CompType: Capacitor; Cap_F: 100nF; IRMS_A: 5.3dA; AEC Category: Q200
C16 = CMP-0006275-2: CAP, CERM, 2.2 uF, 16 V, +/- 10%, X5R, 0402; Manufacturer: TDK; TaMin_C: -55°C; Polarized: N; SizeAreaWB_mm2: 3; Value1: Unknown; U/M: EA; Value: 2.2uF; TaMax_C: 85°C; SizeZ_mm: 0.6; SizeX_mm: 1; SizeY_mm: 0.5; Value2: 16V; CompType: Capacitor; Cap_F: 2.2µF; AEC Category: Q200
D1 = CMP-0002834-1: LED, Green, SMD; Manufacturer: Lumex; Io_A: 20mA; Tjmax_C: 85°C; Value1: W; U/M: EA; Vf_V: 2.2V
D2 = CMP-0086159-1: LED, Red, SMD; Manufacturer: Everlight; SizeArea_mm2: 1.28; Tjmax_C: 85°C; Angle: 120; SizeZ_mm: 0.5; Value1: 0.06W; Ir_A: 10µA; SizeX_mm: 1.6; Io_A: 5mA; Vf_V: 1.95V; SizeY_mm: 0.8; Vr_V: 5V; Power_TotalModule: 60mW; SizeAreaWB_mm2: 4.68
J2 J6 = CMP-0075533-1: Header, 1.27 mm, 5x2, Gold, TH; PartNumber: FTSH-105-01-F-D-K; Manufacturer: Samtec; Alternate Manufacturer: ----; Pitch_mm: 1.27; Gender: Male; Green_REACh: Passed; CT: False; Shrouded: Y; Green_Lifecycle: Active; Row_Count: 2
J3 = CMP-0055564-1: Header, 1.27mm, 7x2, Gold, SMT; PartNumber: FTSH-107-01-F-DV; Manufacturer: Samtec; Alternate Manufacturer: ----; Pitch_mm: 1.27; Gender: Male; Shrouded: N; Row_Count: 2; Current_A: 3.3A; Cert_UL: Y; Green_Lifecycle: Active; Green_REACh: Passed; CNHeader: TRUE; CT: FALSE
J4 = CMP-0075101-1: Footprint for Tag-Connect TC2050 No-Legs cables; PartNumber: TC2050-IDC-NL-FP; CompType: Receptacle; Note: Footprint only, to mate with Tag-Connect TC2050 No-Legs cables; CT: False
R1 R13 R19 = CMP-0026852-3: RES, 1.0 k, 5%, 0.063 W, AEC-Q200 Grade 0, 0402; PartNumber: CRCW04021K00JNED; Manufacturer: Vishay-Dale; CompType: Resistor; Value: 1.0k; Res_ohm: 1k; Value_Code: 1k00; Power_W: 63mW; Value2: 0.063W; VDC_V: 50V; TempCo: 200 ppm/C; EIA_Code: E24; SizeX_mm: 1; SizeY_mm: 0.5; SizeZ_mm: 0.6; AEC Qualified: Y; AEC Category: Q200; AEC Grade: 0
R2 R4 R6-R10 = CMP-0026696-1: as R34 on sheet MCU065E1_XDS110_Circuit
R3 = CMP-0026992-3: RES, 0, 5%, 0.1 W, AEC-Q200 Grade 0, 0402; Manufacturer: Panasonic; Power_W: 100mW; TempCo: 600 ppm/C; Value_Code: 0000; Value: 0; EIA_Code: E24; SizeX_mm: 1; SizeY_mm: 0.5; SizeZ_mm: 0.6; Value2: 0.1W; CompType: Resistor; AEC Qualified: Y; VDC_V: 50V; AEC Category: Q200; SizeAreaWB_mm2: 3
R5 = CMP-0026824-3: RES, 100, 5%, 0.063 W, AEC-Q200 Grade 0, 0402; Manufacturer: Vishay-Dale; Power_W: 63mW; TempCo: 200 ppm/C; Value_Code: 100R; Value: 100; EIA_Code: E24; SizeX_mm: 1; SizeY_mm: 0.5; SizeZ_mm: 0.6; Value2: 0.063W; CompType: Resistor; AEC Qualified: Y; VDC_V: 50V; AEC Category: Q200; AEC Grade: 0
R11 = CMP-0026905-2: RES, 330 k, 5%, 0.063 W, AEC-Q200 Grade 0, 0402; Manufacturer: Vishay-Dale; Power_W: 63mW; TempCo: 200 ppm/C; Value: 330k; EIA_Code: E24; SizeX_mm: 1; SizeY_mm: 0.5; SizeZ_mm: 0.6; Value2: 0.063W; CompType: Resistor; AEC Qualified: Y; VDC_V: 50V; AEC Category: Q200; AEC Grade: 0
R12 = CMP-0026877-2: RES, 220 k, 5%, 0.063 W, AEC-Q200 Grade 0, 0402; Manufacturer: Vishay-Dale; Power_W: 63mW; TempCo: 200 ppm/C; Value: 220k; EIA_Code: E24; SizeX_mm: 1; SizeY_mm: 0.5; SizeZ_mm: 0.6; Value2: 0.063W; CompType: Resistor; AEC Qualified: Y; VDC_V: 50V; AEC Category: Q200; AEC Grade: 0
R14 R15 = CMP-0025756-4: RES, 220, 5%, 0.1 W, AEC-Q200 Grade 0, 0603; Manufacturer: Vishay-Dale; Power_W: 100mW; TempCo: 200 ppm/C; Value_Code: 220R; Value: 220; EIA_Code: E24; SizeX_mm: 1.6; SizeY_mm: 0.8; SizeZ_mm: 1; Value2: 0.1W; SizeArea_mm2: 1.28; CompType: Resistor; AEC Qualified: Y; VDC_V: 75V; AEC Category: Q200; AEC Grade: 0
R16-R18 R20 R26 = CMP-0026852-3: RES, 1.0 k, 5%, 0.063 W, AEC-Q200 Grade 0, 0402; Manufacturer: Vishay-Dale; Power_W: 63mW; TempCo: 200 ppm/C; Value_Code: 1k00; Value: 1.0k; EIA_Code: E24; Res_ohm: 1k; SizeX_mm: 1; SizeY_mm: 0.5; SizeZ_mm: 0.6; Value2: 0.063W; CompType: Resistor; AEC Qualified: Y; VDC_V: 50V; AEC Category: Q200; AEC Grade: 0
R21 = CMP-0025787-4: RES, 33, 5%, 0.1 W, AEC-Q200 Grade 0, 0603; PartNumber: CRCW060333R0JNEA; Manufacturer: Vishay-Dale; Alternate Manufacturer: YAGEO; Alternate PartNumber: RC0603JR-0733RL; CompType: Resistor; Value: 33; Value_Code: 33R0; Power_W: 100mW; Value2: 0.1W; VDC_V: 75V; TempCo: 200 ppm/C; EIA_Code: E24; SizeX_mm: 1.6; SizeY_mm: 0.8; SizeZ_mm: 1; SizeArea_mm2: 1.28; AEC Qualified: Y; AEC Category: Q200; AEC Grade: 0
R22 = CMP-0025787-4: RES, 33, 5%, 0.1 W, AEC-Q200 Grade 0, 0603; PartNumber: CRCW060333R0JNEA; Manufacturer: Vishay-Dale; Alternate Manufacturer: YAGEO; Alternate PartNumber: RC0603JR-0733RL; Value: 33; Value_Code: 33R0; Power_W: 100mW; Value2: 0.1W; VDC_V: 75V; TempCo: 200 ppm/C; EIA_Code: E24; SizeX_mm: 1.6; SizeY_mm: 0.8; SizeZ_mm: 1; SizeArea_mm2: 1.28; AEC Qualified: Y; AEC Category: Q200; AEC Grade: 0
R23 = CMP-0026946-3: RES, 51, 5%, 0.063 W, AEC-Q200 Grade 0, 0402; Manufacturer: Vishay-Dale; Power_W: 63mW; TempCo: 200 ppm/C; Value_Code: 51R0; Value: 51; EIA_Code: E24; SizeX_mm: 1; SizeY_mm: 0.5; SizeZ_mm: 0.6; Value2: 0.063W; CompType: Resistor; AEC Qualified: Y; VDC_V: 50V; AEC Category: Q200; AEC Grade: 0
R24 = CMP-0026825-5: as R29 on sheet MCU065E1_XDS110_Circuit
R25 = CMP-0025951-3: RES, 100, 1%, 0.063 W, AEC-Q200 Grade 0, 0402; Manufacturer: Vishay-Dale; Power_W: 63mW; TempCo: 100 ppm/C; Value_Code: 100R; Value: 100; EIA_Code: E96; SizeX_mm: 1; SizeY_mm: 0.5; SizeZ_mm: 0.6; Value2: 0.063W; CompType: Resistor; AEC Qualified: Y; VDC_V: 50V; AEC Category: Q200; AEC Grade: 0
R27 = CMP-0022457-4: RES, 4.87 k, 1%, 0.1 W, AEC-Q200 Grade 0, 0603; Manufacturer: Vishay-Dale; Power_W: 100mW; TempCo: 100 ppm/C; Value_Code: 4k87; Value: 4.87k; EIA_Code: E96; SizeX_mm: 1.6; SizeY_mm: 0.8; SizeZ_mm: 1; Value2: 0.1W; SizeArea_mm2: 1.28; CompType: Resistor; AEC Qualified: Y; VDC_V: 75V; AEC Category: Q200; AEC Grade: 0
TP1 = CMP-0078143-2: TEST POINT.  No entry in BOM.
U1 = CMP-0077953-1: MSP432E401YTPDT, PDT0128A (TQFP-128); Alternate PartNumber: MSP432E401YTPDTR; Alternate Manufacturer: Texas Instruments; SizeAreaWB_mm2: 324; SizeZ_mm: 1.2; SizeX_mm: 16; SizeArea_mm2: 256; CompType: IC; AEC Qualified: N; AEC Category: Q200
U2 = CMP-0033095-1: Precision Micropower Shunt Voltage Reference, 0.2% accuracy, 2.5 V, 15 ppm / degC, 15 mA, -40 to 85 degC, 3-pin SOT-23 (DBZ), Green (RoHS & no Sb/Br); Manufacturer: Texas Instruments; VO(V): 2.5; Iout/Iz(Max)(mA): 15; Temp Coeff(Max)(ppm/ degree C): 100; Min Iz for Regulation(uA): 75; Rating: Catalog; Initial Accuracy @ 25/deg C(%): 0.2
Y1 = CMP-0004648-3: Crystal, 16 MHz, 18 pF, SMD; PartNumber: ABM3-16.000MHZ-D2Y-T; Manufacturer: Abracon Corporation; Alternate Manufacturer: ----; TaMin_C: -40°C; TaMax_C: 85°C; Frequency Stability: +/-30ppm

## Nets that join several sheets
GND: MCU065E1_EngineArea (30 pins), MCU065E1_Host_Interface (22 pins), MCU065E1_LEDs_Switches_Sensors (23 pins), MCU065E1_XDS110_Circuit (30 pins), MCU065E1_XDS110_Host (46 pins)
VBAT_CC: MCU065E1_EngineArea (9 pins), MCU065E1_Host_Interface (Q2.2 R57.1 R104.2), MCU065E1_XDS110_Circuit (C27.1 C28.1 J10.1), MCU065E1_XDS110_Host (J3.3 J3.4 R19.2)
VBUS_USB1: MCU065E1_XDS110_Circuit (5 pins), MCU065E1_XDS110_Host (R5.2 R11.2)
VCC_BRD: MCU065E1_EngineArea (J16.3 R38.2), MCU065E1_Host_Interface (J21.1 R58.1), MCU065E1_LEDs_Switches_Sensors (13 pins), MCU065E1_XDS110_Circuit (J7.1 J8.2), MCU065E1_XDS110_Host (R1.1)
VCC_LDO_3V3: MCU065E1_XDS110_Circuit (14 pins), MCU065E1_XDS110_Host (31 pins)
VCC_MCU_5V: MCU065E1_Host_Interface (J19.1 P1.21), MCU065E1_XDS110_Circuit (J9.1)
CC_nRESET: MCU065E1_EngineArea (CC1.35 J14.2), MCU065E1_LEDs_Switches_Sensors (D6.1), MCU065E1_XDS110_Circuit (J5.10 Q1.1 SW1.2), MCU065E1_XDS110_Host (J6.10)
LP_GPIO_01: MCU065E1_Host_Interface (R89.2), MCU065E1_XDS110_Circuit (J11.1)
LP_GPIO_02: MCU065E1_Host_Interface (C37.1 R106.2 R111.2), MCU065E1_XDS110_Circuit (J12.1)
LP_RESET_OUT: MCU065E1_Host_Interface (P2.16), MCU065E1_LEDs_Switches_Sensors (D6.2 R142.1)
P01_GPIO_10: MCU065E1_EngineArea (CC1.3), MCU065E1_Host_Interface (R62.1 R86.1), MCU065E1_LEDs_Switches_Sensors (Q6.1 R130.1 R151.2), MCU065E1_XDS110_Host (J3.9)
P02_GPIO_11: MCU065E1_EngineArea (CC1.4), MCU065E1_Host_Interface (R60.1 R90.1), MCU065E1_LEDs_Switches_Sensors (Q5.1 R137.1 R150.2), MCU065E1_XDS110_Host (J3.11)
P03_GPIO_12: MCU065E1_EngineArea (CC1.9), MCU065E1_Host_Interface (R68.1 R102.1)
P04_GPIO_13: MCU065E1_EngineArea (CC1.10), MCU065E1_Host_Interface (R64.1 R103.1), MCU065E1_LEDs_Switches_Sensors (R133.1 R155.2 SW2.1)
P05_GPIO_14: MCU065E1_EngineArea (CC1.5), MCU065E1_Host_Interface (R78.1)
P06_GPIO_15: MCU065E1_EngineArea (CC1.6), MCU065E1_Host_Interface (R81.2 R96.2)
P07_GPIO_16: MCU065E1_EngineArea (CC1.7), MCU065E1_Host_Interface (R77.2 R99.2)
P08_GPIO_17: MCU065E1_EngineArea (CC1.8), MCU065E1_Host_Interface (R67.2)
P15_GPIO_22: MCU065E1_EngineArea (CC1.11), MCU065E1_Host_Interface (R93.2), MCU065E1_LEDs_Switches_Sensors (R156.2 SW3.1)
P16_GPIO_23: MCU065E1_EngineArea (R46.1), MCU065E1_Host_Interface (R88.1 R97.1), MCU065E1_LEDs_Switches_Sensors (R134.1)
P16_JTAG_TDI: MCU065E1_EngineArea (CC1.12 R46.2), MCU065E1_XDS110_Circuit (J5.2), MCU065E1_XDS110_Host (J6.8)
P17_GPIO_24: MCU065E1_EngineArea (R45.1), MCU065E1_Host_Interface (R66.1 R92.1 R100.1), MCU065E1_LEDs_Switches_Sensors (R139.1)
P17_JTAG_TDO: MCU065E1_EngineArea (CC1.18 R45.2), MCU065E1_XDS110_Circuit (J5.4), MCU065E1_XDS110_Host (J6.6)
P18_GPIO_28: MCU065E1_EngineArea (CC1.19), MCU065E1_Host_Interface (R63.2 R76.1)
P19_JTAG_TCK: MCU065E1_EngineArea (CC1.21 R47.2), MCU065E1_XDS110_Circuit (J5.6), MCU065E1_XDS110_Host (J6.4)
P20_JTAG_TMS: MCU065E1_EngineArea (CC1.22), MCU065E1_XDS110_Circuit (J5.8), MCU065E1_XDS110_Host (J6.2)
P21_GPIO_25: MCU065E1_EngineArea (R51.2), MCU065E1_Host_Interface (R73.1 R85.2)
P50_GPIO_00: MCU065E1_EngineArea (CC1.44), MCU065E1_Host_Interface (R54.1 R55.1 R91.2 R95.1)
P53_GPIO_30: MCU065E1_EngineArea (CC1.42), MCU065E1_Host_Interface (R83.2)
P55_GPIO_01: MCU065E1_EngineArea (CC1.46), MCU065E1_XDS110_Circuit (J11.2), MCU065E1_XDS110_Host (R22.1)
P57_GPIO_02: MCU065E1_EngineArea (CC1.47), MCU065E1_XDS110_Circuit (J12.2), MCU065E1_XDS110_Host (R21.1)
P58_GPIO_03: MCU065E1_EngineArea (CC1.48), MCU065E1_Host_Interface (R53.1 R56.1 R121.2)
P59_GPIO_04: MCU065E1_EngineArea (CC1.49), MCU065E1_Host_Interface (R59.2 R118.2)
P60_GPIO_05: MCU065E1_EngineArea (CC1.50), MCU065E1_Host_Interface (5 pins)
P61_GPIO_06: MCU065E1_EngineArea (CC1.51), MCU065E1_Host_Interface (R71.1 R101.1)
P62_GPIO_07: MCU065E1_EngineArea (CC1.52), MCU065E1_Host_Interface (R80.1 R82.1 R98.1)
P63_GPIO_08: MCU065E1_EngineArea (CC1.53), MCU065E1_Host_Interface (R79.2)
P64_GPIO_09: MCU065E1_EngineArea (CC1.54), MCU065E1_Host_Interface (R70.1 R87.2), MCU065E1_LEDs_Switches_Sensors (Q7.1 R152.2)
SOP0: MCU065E1_EngineArea (CC1.34 J18.2), MCU065E1_LEDs_Switches_Sensors (Q3.3)
SOP1: MCU065E1_EngineArea (CC1.24 J18.4), MCU065E1_LEDs_Switches_Sensors (Q3.6)
XDS_CC_nRESET: MCU065E1_XDS110_Circuit (J5.9 R29.1), MCU065E1_XDS110_Host (J2.10)
XDS_JTAG_TCK: MCU065E1_XDS110_Circuit (J5.5), MCU065E1_XDS110_Host (J2.4 R6.1)
XDS_JTAG_TDI: MCU065E1_XDS110_Circuit (J5.1), MCU065E1_XDS110_Host (J2.8 R9.1)
XDS_JTAG_TDO: MCU065E1_XDS110_Circuit (J5.3), MCU065E1_XDS110_Host (J2.6 R8.1)
XDS_JTAG_TMS: MCU065E1_XDS110_Circuit (J5.7), MCU065E1_XDS110_Host (J2.2 R7.1)
XDS_nRESET: MCU065E1_XDS110_Circuit (U3.4), MCU065E1_XDS110_Host (R10.1)
XDS_UART_RX: MCU065E1_XDS110_Circuit (R34.2), MCU065E1_XDS110_Host (R2.1)
XDS_UART_TX: MCU065E1_XDS110_Circuit (U7.4), MCU065E1_XDS110_Host (R4.1)
XDSET_ID: MCU065E1_XDS110_Circuit (J1.4), MCU065E1_XDS110_Host (R3.2)
XDSET_N: MCU065E1_XDS110_Circuit (J1.2 U4.1 U4.10), MCU065E1_XDS110_Host (U1.93)
XDSET_P: MCU065E1_XDS110_Circuit (J1.3 U4.2 U4.9), MCU065E1_XDS110_Host (U1.94)

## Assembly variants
001: not fitted FID1 FID2 FID3 J4 J14 J26 J27 J28 Q2 R38 R39 R40 R41 R42 R43 R47 R58 R59 R60 R61 R62 R66 R70 R73 R74 R76 R80 R84 R94 R95 R96 R97 R98 R99 R100 R101 R102 R103 R105 R106 R107 R114 R115 R129 R132 R133 R134 R139 U9
002: not fitted FID1 FID2 FID3 J4 J14 J26 J27 J28 Q2 R38 R39 R40 R41 R42 R43 R47 R58 R59 R60 R61 R62 R66 R70 R73 R74 R76 R80 R84 R94 R95 R96 R97 R98 R99 R100 R101 R102 R103 R105 R106 R107 R114 R115 R129 R132 R133 R134 R139 U9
